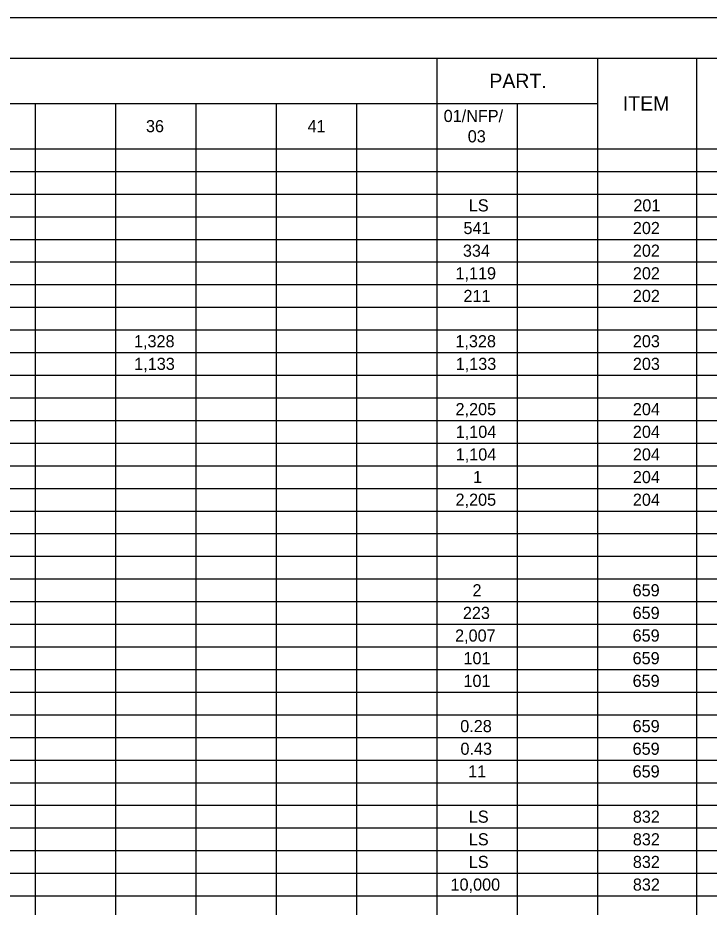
# Model space of a CAD drawing. Extents: x 0 to 34, y 0 to 22.
# Drawn here: x 8.56 to 17.11, y 11 to 22 of the extents above; entities that cross this region are included whole.
import ezdxf

# ---------------------------------------------------------------- set-up
doc = ezdxf.new("R2010")
doc.units = 0
for name, color, linetype in [('SH_Border', 7, 'Continuous'), ('SH_Cut_Line', 7, 'Continuous'), ('SH_Text', 7, 'Continuous')]:
    doc.layers.add(name, color=color, linetype=linetype)

msp = doc.modelspace()

# ---------------------------------------------------------------- linework, layer by layer
at = {"layer": 'SH_Border'}
msp.add_lwpolyline([(1.5, 21.5), (33.5, 21.5), (33.5, 0.5), (1.5, 0.5)], close=True, dxfattribs=at)
at = {"layer": 'SH_Cut_Line'}
msp.add_lwpolyline([(0, 0), (34, 0), (34, 22), (0, 22)], close=True, dxfattribs=at)
at = {"layer": 'SH_Text'}
for p, q in [((1.5, 21.5), (32, 21.5)), ((13.742, 21.5), (13.742, 0.5)), ((15.731, 21.5), (15.731, 0.5)), ((16.954, 21.5), (16.954, 0.5)), ((1.5, 20.94), (15.731, 20.94)), ((8.77, 20.94), (8.77, 0.5)), ((9.765, 20.94), (9.765, 0.5)), ((10.759, 20.94), (10.759, 0.5)), ((11.753, 20.94), (11.753, 0.5)), ((12.748, 20.94), (12.748, 0.5)), ((14.737, 20.94), (14.737, 0.5)), ((1.5, 20.38), (32, 20.38)), ((1.5, 20.1), (32, 20.1)), ((1.5, 19.82), (32, 19.82)), ((1.5, 19.54), (32, 19.54)), ((1.5, 19.26), (32, 19.26)), ((1.5, 18.98), (32, 18.98)), ((1.5, 18.7), (32, 18.7)), ((1.5, 18.42), (32, 18.42)), ((1.5, 18.14), (32, 18.14)), ((1.5, 17.86), (32, 17.86)), ((1.5, 17.58), (32, 17.58)), ((1.5, 17.3), (32, 17.3)), ((1.5, 17.02), (32, 17.02)), ((1.5, 16.74), (32, 16.74)), ((1.5, 16.46), (32, 16.46)), ((1.5, 16.18), (32, 16.18)), ((1.5, 15.9), (32, 15.9)), ((1.5, 15.62), (32, 15.62)), ((1.5, 15.34), (32, 15.34)), ((1.5, 15.06), (32, 15.06)), ((1.5, 14.78), (32, 14.78)), ((1.5, 14.5), (32, 14.5)), ((1.5, 14.22), (32, 14.22)), ((1.5, 13.94), (32, 13.94)), ((1.5, 13.66), (32, 13.66)), ((1.5, 13.38), (32, 13.38)), ((1.5, 13.1), (32, 13.1)), ((1.5, 12.82), (32, 12.82)), ((1.5, 12.54), (32, 12.54)), ((1.5, 12.26), (32, 12.26)), ((1.5, 11.98), (32, 11.98)), ((1.5, 11.7), (32, 11.7)), ((1.5, 11.42), (32, 11.42)), ((1.5, 11.14), (32, 11.14))]:
    msp.add_line(p, q, dxfattribs=at)

# ---------------------------------------------------------------- texts
for s, height, p in [('PART.', 0.18, (14.392, 21.13)), ('ITEM', 0.18, (16.043, 20.85)), ('01/NFP/', 0.15, (13.826, 20.711)), ('36', 0.15, (10.142, 20.585)), ('41', 0.15, (12.142, 20.585)), ('03', 0.15, (14.124, 20.459)), ('LS', 0.15, (14.137, 19.605)), ('201', 0.15, (16.173, 19.605)), ('541', 0.15, (14.071, 19.325)), ('202', 0.15, (16.167, 19.325)), ('334', 0.15, (14.064, 19.045)), ('202', 0.15, (16.167, 19.045)), ('1,119', 0.15, (13.972, 18.765)), ('202', 0.15, (16.167, 18.765)), ('211', 0.15, (14.071, 18.485)), ('202', 0.15, (16.167, 18.485)), ('1,328', 0.15, (9.994, 17.925)), ('1,328', 0.15, (13.971, 17.925)), ('203', 0.15, (16.167, 17.925)), ('1,133', 0.15, (9.997, 17.645)), ('1,133', 0.15, (13.975, 17.645)), ('203', 0.15, (16.167, 17.645)), ('2,205', 0.15, (13.973, 17.085)), ('204', 0.15, (16.167, 17.085)), ('1,104', 0.15, (13.975, 16.805)), ('204', 0.15, (16.167, 16.805)), ('1,104', 0.15, (13.975, 16.525)), ('204', 0.15, (16.167, 16.525)), ('1', 0.15, (14.19, 16.245)), ('204', 0.15, (16.167, 16.245)), ('2,205', 0.15, (13.973, 15.965)), ('204', 0.15, (16.167, 15.965)), ('2', 0.15, (14.183, 14.845)), ('659', 0.15, (16.164, 14.845)), ('223', 0.15, (14.064, 14.565)), ('659', 0.15, (16.164, 14.565)), ('2,007', 0.15, (13.967, 14.285)), ('659', 0.15, (16.164, 14.285)), ('101', 0.15, (14.071, 14.005)), ('659', 0.15, (16.164, 14.005)), ('101', 0.15, (14.071, 13.725)), ('659', 0.15, (16.164, 13.725)), ('0.28', 0.15, (14.031, 13.165)), ('659', 0.15, (16.164, 13.165)), ('0.43', 0.15, (14.034, 12.885)), ('659', 0.15, (16.164, 12.885)), ('11', 0.15, (14.13, 12.605)), ('659', 0.15, (16.164, 12.605)), ('LS', 0.15, (14.137, 12.045)), ('832', 0.15, (16.167, 12.045)), ('LS', 0.15, (14.137, 11.765)), ('832', 0.15, (16.167, 11.765)), ('LS', 0.15, (14.137, 11.485)), ('832', 0.15, (16.167, 11.485)), ('10,000', 0.15, (13.911, 11.205)), ('832', 0.15, (16.167, 11.205))]:
    msp.add_text(s, height=height, dxfattribs=at).set_placement(p)

doc.saveas('drawing.dxf')
